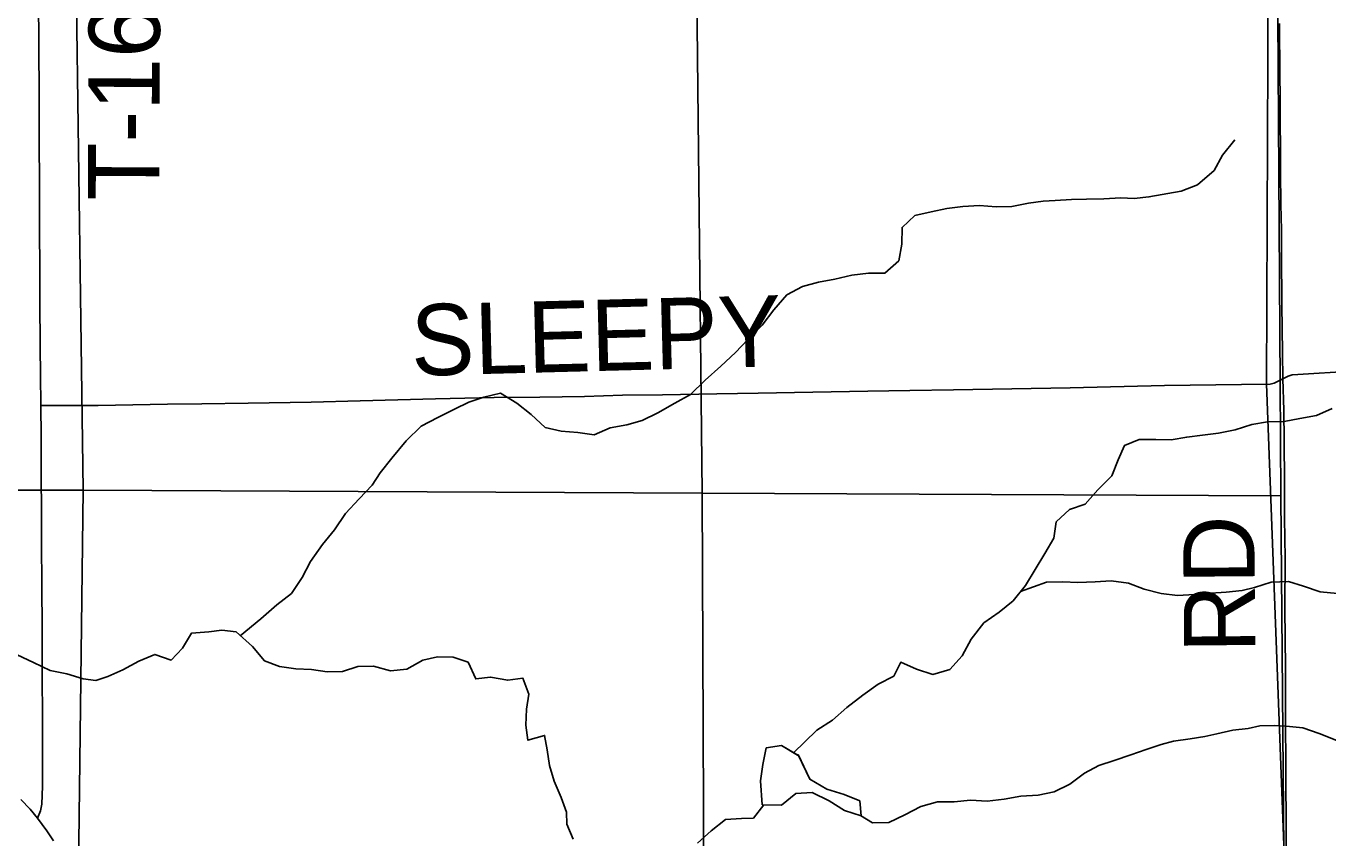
# Model space of a CAD drawing. Extents: x 0 to 34, y 0 to 22.
# Drawn here: x 3.782 to 4.301, y 18.189 to 18.513 of the extents above; entities that cross this region are included whole.
import ezdxf

# ---------------------------------------------------------------- set-up
doc = ezdxf.new("R2010")
doc.units = 0
for name, color, linetype in [('GM_X_County_Road', 7, 'Continuous'), ('GM_X_County_Road_Text', 7, 'Continuous'), ('GM_X_Minor_Lake', 7, 'Continuous'), ('GM_X_Minor_River', 7, 'Continuous'), ('GM_X_Rail_Line_Text', 7, 'Continuous'), ('GM_X_Section', 7, 'Continuous'), ('GM_X_Township', 7, 'Continuous'), ('GM_X_Township_Road', 7, 'Continuous'), ('GM_X_Township_Road_Text', 7, 'Continuous')]:
    doc.layers.add(name, color=color, linetype=linetype)

msp = doc.modelspace()

# ---------------------------------------------------------------- linework, layer by layer
at = {"layer": 'GM_X_County_Road'}
for points in [[(4.28436, 18.1673), (4.28432, 18.1917), (4.28413, 18.21502), (4.28399, 18.23811), (4.28403, 18.25653), (4.2838, 18.28032), (4.28385, 18.30033), (4.28368, 18.31626), (4.28361, 18.33094), (4.28352, 18.34702), (4.28333, 18.35936), (4.28296, 18.37194), (4.28288, 18.38231), (4.28262, 18.40152), (4.28247, 18.4219), (4.2824, 18.43134), (4.28221, 18.4415), (4.28212, 18.45443), (4.28204, 18.46436), (4.28197, 18.47369), (4.28188, 18.48467), (4.28181, 18.49279), (4.28167, 18.5137)], [(3.78614, 18.19655), (3.7831, 18.20014), (3.77942, 18.20399)], [(3.7925, 18.18753), (3.78987, 18.1915), (3.78614, 18.19655)]]:
    msp.add_lwpolyline(points, dxfattribs=at)
at = {"layer": 'GM_X_Minor_Lake'}
for points in [[(4.08975, 18.22155), (4.08293, 18.22554), (4.07685, 18.22463), (4.07549, 18.21798), (4.07451, 18.21151), (4.07526, 18.20197)], [(4.08934, 18.22179), (4.08293, 18.22554), (4.07685, 18.22463), (4.07549, 18.21798), (4.07451, 18.21151), (4.07526, 18.20197)], [(4.07526, 18.20197), (4.083, 18.20177), (4.08873, 18.20649), (4.09518, 18.20683), (4.102, 18.20356), (4.10806, 18.19972), (4.1147, 18.1976), (4.11416, 18.2035), (4.1079, 18.206), (4.10108, 18.20813), (4.09426, 18.21216), (4.08954, 18.22198)], [(4.07526, 18.20197), (4.083, 18.20177), (4.08873, 18.20649), (4.09518, 18.20683), (4.102, 18.20356), (4.10806, 18.19972), (4.1147, 18.1976), (4.11416, 18.2035), (4.1079, 18.206), (4.10108, 18.20813), (4.09426, 18.21216), (4.08975, 18.22155)]]:
    msp.add_lwpolyline(points, dxfattribs=at)
at = {"layer": 'GM_X_Minor_River'}
for points in [[(3.86701, 18.26931), (3.87519, 18.27617), (3.88162, 18.28171), (3.88749, 18.2863), (3.89164, 18.29259), (3.89503, 18.29907), (3.89974, 18.30574), (3.90465, 18.31166), (3.90899, 18.31814), (3.91447, 18.32406), (3.91957, 18.3294), (3.92278, 18.33436), (3.9275, 18.34027), (3.93317, 18.34714), (3.93922, 18.35306), (3.94585, 18.35651), (3.95248, 18.35976), (3.95816, 18.36264), (3.96423, 18.36456), (3.97087, 18.36611), (3.97735, 18.36214), (3.98307, 18.35759), (3.9886, 18.35248), (3.99507, 18.35098), (4.00172, 18.35043), (4.00818, 18.34951), (4.01462, 18.35238), (4.02127, 18.35355), (4.02733, 18.35528), (4.03359, 18.35835), (4.04041, 18.36218), (4.04666, 18.36562), (4.05252, 18.37135), (4.05876, 18.37689), (4.06462, 18.38243), (4.06954, 18.38758), (4.07521, 18.39331), (4.07993, 18.39941), (4.08503, 18.40533), (4.09128, 18.40878), (4.09773, 18.41051), (4.10418, 18.41168), (4.11101, 18.41322), (4.11766, 18.41401), (4.12412, 18.41403), (4.12979, 18.419), (4.1309, 18.42566), (4.13106, 18.43232), (4.13616, 18.43709), (4.14262, 18.43845), (4.14888, 18.4398), (4.15533, 18.44059), (4.16198, 18.44099), (4.16863, 18.44044), (4.17489, 18.44066), (4.18154, 18.44201), (4.18742, 18.4428), (4.19217, 18.443), (4.19862, 18.44341), (4.2047, 18.44362), (4.21154, 18.44364), (4.21837, 18.44405), (4.22369, 18.44388), (4.22958, 18.44447), (4.24248, 18.4468), (4.24893, 18.4493), (4.25555, 18.45503), (4.25894, 18.46113), (4.26385, 18.46723)], [(4.08756, 18.22258), (4.09705, 18.23171), (4.1033, 18.23573), (4.10898, 18.2407), (4.11541, 18.24567), (4.12147, 18.25006), (4.12772, 18.25332), (4.13054, 18.25884), (4.13682, 18.25601), (4.14329, 18.25395), (4.15012, 18.25587), (4.15503, 18.26141), (4.15861, 18.26808), (4.16371, 18.27456), (4.16977, 18.27877), (4.17544, 18.28336), (4.18035, 18.28946), (4.18412, 18.29575), (4.18808, 18.30223), (4.19166, 18.30833), (4.19258, 18.3148), (4.19787, 18.31977), (4.20413, 18.32188), (4.20923, 18.32761), (4.21472, 18.33314), (4.21734, 18.33962), (4.21979, 18.34534), (4.22566, 18.34764), (4.23231, 18.34766), (4.23839, 18.3475), (4.24465, 18.34866), (4.25092, 18.34944), (4.25737, 18.35023), (4.26401, 18.35158), (4.27065, 18.3537), (4.27691, 18.35468), (4.28356, 18.35489), (4.28982, 18.35605), (4.29646, 18.35722), (4.30272, 18.36009)], [(4.17836, 18.28708), (4.1887, 18.29082), (4.19516, 18.29085), (4.20124, 18.29068), (4.20808, 18.29089), (4.21453, 18.2913), (4.22137, 18.29037), (4.22765, 18.28792), (4.2345, 18.28623), (4.24096, 18.2855), (4.2478, 18.2859), (4.25425, 18.28631), (4.26033, 18.28671), (4.26678, 18.28749), (4.27172, 18.28865), (4.27835, 18.29077), (4.28519, 18.29098), (4.29128, 18.2891), (4.29794, 18.28685), (4.30478, 18.2863)], [(3.77801, 18.26174), (3.78448, 18.25872), (3.79115, 18.25551), (3.7978, 18.2542), (3.80427, 18.25213), (3.8094, 18.25158), (3.81414, 18.25312), (3.8202, 18.25581), (3.82646, 18.25925), (3.8329, 18.26194), (3.83937, 18.25968), (3.8439, 18.26445), (3.84749, 18.27036), (3.85451, 18.27096), (3.85964, 18.27155), (3.86534, 18.271), (3.87182, 18.26513), (3.8766, 18.25944), (3.88269, 18.25718), (3.88915, 18.25625), (3.89542, 18.25589), (3.90169, 18.25496), (3.90777, 18.25518), (3.91384, 18.2571), (3.9201, 18.25731), (3.92695, 18.25544), (3.9334, 18.25603), (3.93984, 18.25967), (3.94573, 18.26102), (3.95199, 18.26085), (3.95789, 18.25878), (3.96096, 18.25214), (3.96685, 18.25292), (3.97369, 18.25161), (3.97977, 18.2524), (3.98207, 18.24613), (3.98115, 18.24004), (3.98099, 18.23376), (3.98178, 18.22768), (3.98842, 18.2296), (3.9894, 18.2239), (3.99038, 18.21763), (3.9923, 18.21136), (3.99499, 18.2049), (3.99711, 18.19901), (3.99732, 18.19426), (3.99982, 18.18818)], [(4.11451, 18.19762), (4.11926, 18.1947), (4.12572, 18.19492), (4.13216, 18.19798), (4.1386, 18.20124), (4.14524, 18.20317), (4.15189, 18.20319), (4.15834, 18.20379), (4.16499, 18.20343), (4.17183, 18.20422), (4.17847, 18.20538), (4.1853, 18.20579), (4.19176, 18.20714), (4.19801, 18.21021), (4.20388, 18.2146), (4.20956, 18.21767), (4.21563, 18.21959), (4.22227, 18.2219), (4.22852, 18.22402), (4.2344, 18.22594), (4.23933, 18.22729), (4.24598, 18.22826), (4.25186, 18.22924), (4.2566, 18.2302), (4.26306, 18.23175), (4.26913, 18.23234), (4.27387, 18.2335), (4.27957, 18.23352), (4.28432, 18.23335), (4.29097, 18.23261), (4.29744, 18.23035), (4.30448, 18.22753)], [(4.0494, 18.18665), (4.05489, 18.19162), (4.06056, 18.19601), (4.06702, 18.19641), (4.07177, 18.19662), (4.07592, 18.20196)]]:
    msp.add_lwpolyline(points, dxfattribs=at)
at = {"layer": 'GM_X_Rail_Line_Text'}
msp.add_lwpolyline([(2.77875, 17.80661), (3.04126, 17.80913), (3.53178, 17.8199), (4.04512, 17.83208), (4.17864, 17.83524), (4.28678, 17.83811), (4.28692, 17.84212), (4.28581, 17.95524), (4.28464, 18.15407), (4.27642, 18.36992), (4.27726, 18.56476), (4.27587, 18.8261), (4.27859, 19.13014), (4.27679, 19.3807), (4.2769, 19.4129), (4.27672, 19.50175), (4.27627, 19.60888)], dxfattribs=at)
at = {"layer": 'GM_X_Section'}
for points in [[(3.80064, 18.5989), (3.80425, 18.32752), (3.54412, 18.32749), (3.54284, 18.60193)], [(4.04842, 18.59978), (4.0513, 18.32631), (3.80425, 18.32752), (3.80064, 18.5989)], [(4.28047, 18.60061), (4.2819, 18.36989), (4.28218, 18.32518), (4.0513, 18.32631), (4.04842, 18.59978)], [(3.80425, 18.32752), (3.8013, 18.0787), (3.54907, 18.0763), (3.54412, 18.32749)], [(4.0513, 18.32631), (4.0523, 18.07571), (3.8013, 18.0787), (3.80425, 18.32752)], [(4.28218, 18.32518), (4.28428, 18.07404), (4.0523, 18.07571), (4.0513, 18.32631)]]:
    msp.add_lwpolyline(points, close=True, dxfattribs=at)
at = {"layer": 'GM_X_Township'}
msp.add_lwpolyline([(5.23962, 17.86489), (4.75674, 17.85444), (4.28987, 17.8422), (4.28692, 17.84212), (4.28581, 17.95524), (4.28464, 18.15407), (4.27642, 18.36992), (4.27726, 18.56476), (4.27587, 18.8261), (4.27859, 19.13014), (4.27679, 19.3807), (4.2769, 19.4129), (4.27672, 19.50175), (4.27627, 19.60888)], dxfattribs=at)
at = {"layer": 'GM_X_Township_Road'}
for points in [[(3.78614, 18.19655), (3.78731, 18.19953), (3.78785, 18.20225), (3.78811, 18.20932), (3.78807, 18.22097), (3.78803, 18.23052), (3.78795, 18.25971), (3.78791, 18.2718), (3.78782, 18.29), (3.78773, 18.30588), (3.78763, 18.32004), (3.78755, 18.33209), (3.7875, 18.34884), (3.78747, 18.3612), (3.78729, 18.37351), (3.78713, 18.38451), (3.78706, 18.40331), (3.78701, 18.41665), (3.78691, 18.43038), (3.78683, 18.44201), (3.78676, 18.47433), (3.7867, 18.4872), (3.78662, 18.50249), (3.7865, 18.52612)], [(4.28296, 18.37194), (4.28511, 18.37292), (4.28675, 18.37345), (4.28894, 18.37367), (4.31044, 18.37496), (4.3269, 18.37599), (4.36243, 18.37568), (4.37805, 18.3758), (4.40256, 18.37592), (4.42333, 18.37605), (4.44318, 18.37629), (4.45692, 18.37637), (4.47959, 18.37662)], [(3.78747, 18.3612), (3.8103, 18.36128), (3.83792, 18.36171), (3.85164, 18.36193), (3.87021, 18.36222), (3.89535, 18.36262), (3.91482, 18.36316), (3.94488, 18.36389), (3.96835, 18.36439), (3.98651, 18.36462), (4.00439, 18.36489), (4.01956, 18.3653), (4.03552, 18.36555), (4.05717, 18.3659), (4.07364, 18.3662), (4.09542, 18.3666), (4.11741, 18.367), (4.13415, 18.36727), (4.15162, 18.36754), (4.17489, 18.3679), (4.19813, 18.36828), (4.23575, 18.36918), (4.26655, 18.3696), (4.27791, 18.36981), (4.27959, 18.3702), (4.2809, 18.37081), (4.28296, 18.37194)]]:
    msp.add_lwpolyline(points, dxfattribs=at)

# ---------------------------------------------------------------- texts
at = {"layer": 'GM_X_County_Road_Text'}
msp.add_text('RD', height=0.028409, rotation=90.4937, dxfattribs=at).set_placement((4.27203, 18.26261))
at = {"layer": 'GM_X_Township_Road_Text'}
for s, rotation, p in [('T-164', 89.7193, (3.83459, 18.44288)), ('SLEEPY', 1.4975, (3.93541, 18.37305))]:
    msp.add_text(s, height=0.028409, rotation=rotation, dxfattribs=at).set_placement(p)

doc.saveas('drawing.dxf')
